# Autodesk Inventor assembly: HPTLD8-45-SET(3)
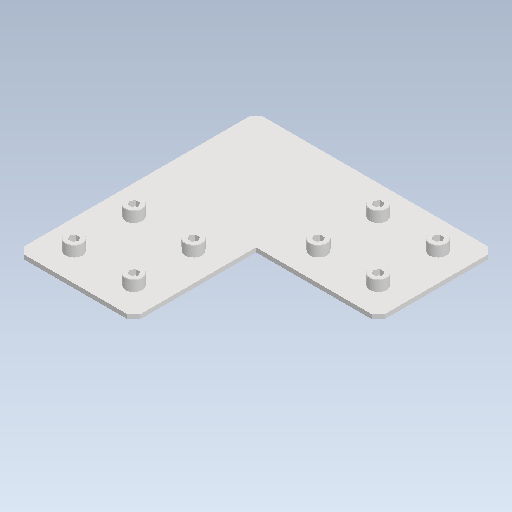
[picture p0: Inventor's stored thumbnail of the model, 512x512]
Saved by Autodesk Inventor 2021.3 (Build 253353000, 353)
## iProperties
Created: 2022-02
Part Number: HPTLD8-45-SET(3)
Document SubType Name: Assembly
Designer: kengo
Author: kengo
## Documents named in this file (4)
- C:\Users\kengo\Documents\S2S_frame\SDC345\frame_misumi_ver12\HPTLD8-45-SET(3).iam
- C:\Users\kengo\Documents\S2S_frame\SDC345\frame_misumi_ver12\HPTLD8-45.ipt
- C:\Users\kengo\Documents\S2S_frame\SDC345\frame_misumi_ver12\HNTT8-8.ipt
- C:\Users\kengo\Documents\S2S_frame\SDC345\frame_misumi_ver12\CBM8-15.ipt
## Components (17 placed, 3 different names)
1. HPTLD8-45
2. HNTT8-8
3. CBM8-15
4. HNTT8-8:1
5. CBM8-15:1
6. HNTT8-8:2
7. CBM8-15:2
8. HNTT8-8:3
9. CBM8-15:3
10. HNTT8-8:4
11. CBM8-15:4
12. HNTT8-8:5
13. CBM8-15:5
14. HNTT8-8:6
15. CBM8-15:6
16. HNTT8-8:7
17. CBM8-15:7
